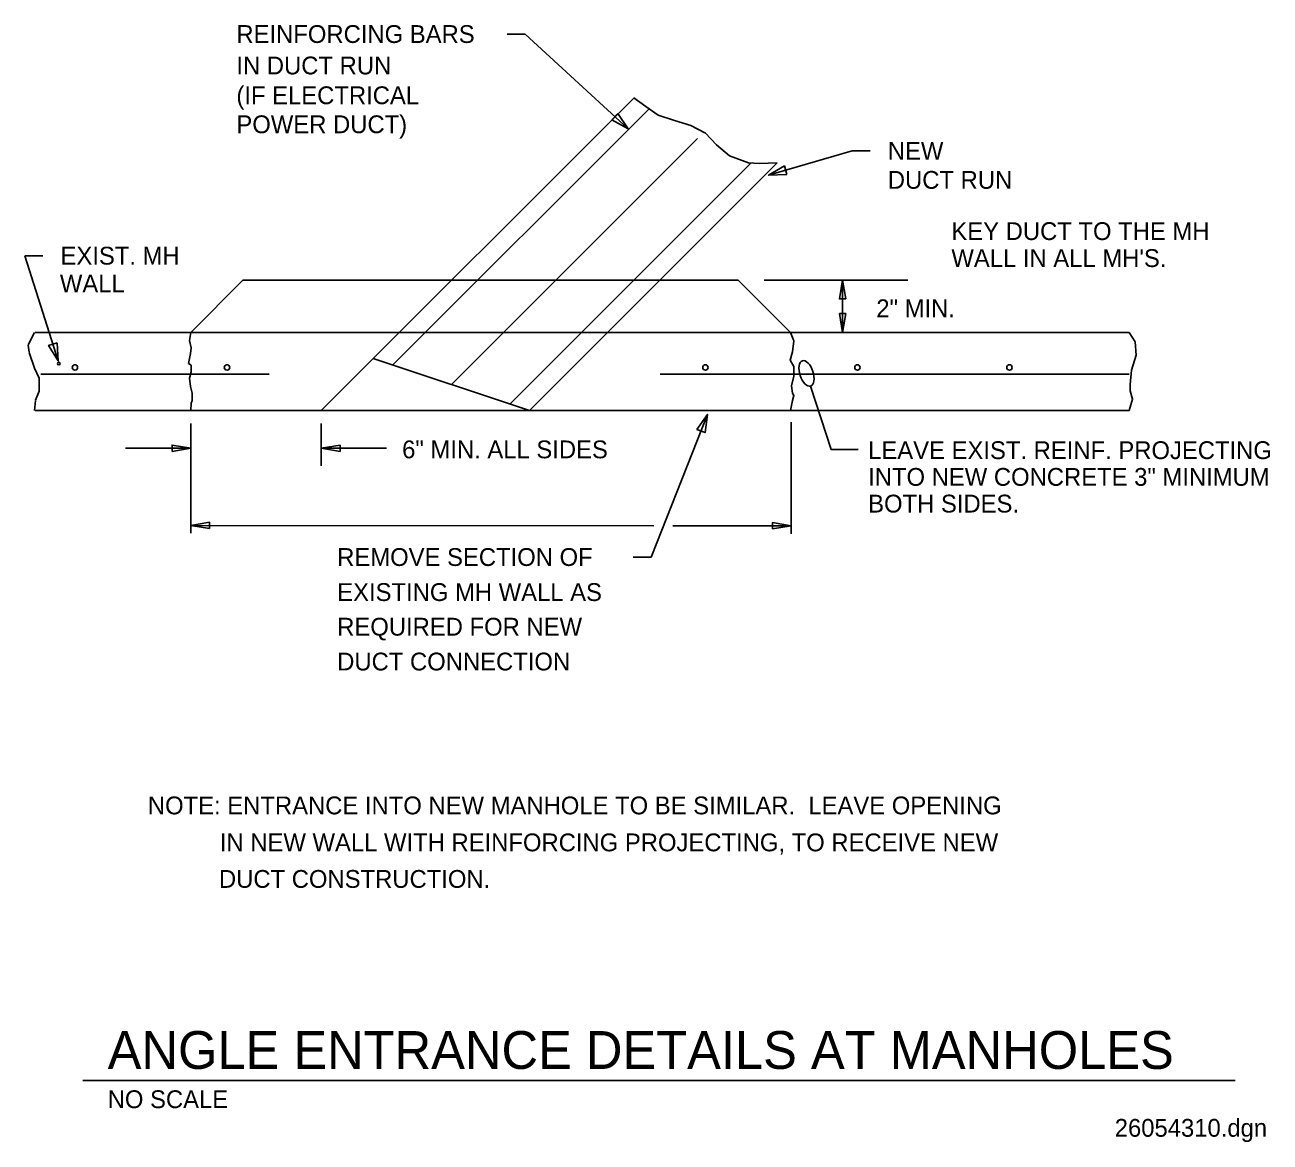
# Model space of a CAD drawing. Extents: x -12484.7 to -12438.1, y -12347.3 to -12305.5.
import ezdxf

# ---------------------------------------------------------------- set-up
doc = ezdxf.new("R2010")
doc.units = 0
for name, color, linetype in [('G-ANNO-TEXT', 7, 'Continuous'), ('G-DETL-LINE', 7, 'Continuous'), ('G-DETL-OTLN', 7, 'Continuous')]:
    doc.layers.add(name, color=color, linetype=linetype)

msp = doc.modelspace()

# ---------------------------------------------------------------- linework, layer by layer
at = {"layer": 'G-ANNO-TEXT'}
for p, q in [((-12466.688, -12305.829), (-12466.021, -12305.829)), ((-12466.021, -12305.829), (-12462.168, -12309.374)), ((-12453.78, -12310.201), (-12456.909, -12311.113)), ((-12453.113, -12310.201), (-12453.78, -12310.201)), ((-12484.072, -12314.128), (-12484.739, -12314.128)), ((-12484.739, -12314.128), (-12483.492, -12318.069)), ((-12457.071, -12315.044), (-12451.702, -12315.047)), ((-12478.532, -12320.412), (-12478.534, -12324.52)), ((-12473.649, -12320.412), (-12473.647, -12321.992)), ((-12461.304, -12325.411), (-12459.199, -12320.071)), ((-12456.059, -12320.361), (-12456.061, -12324.536)), ((-12478.534, -12324.224), (-12461.199, -12324.236)), ((-12460.487, -12324.236), (-12456.061, -12324.239)), ((-12461.971, -12325.411), (-12461.304, -12325.411)), ((-12482.57, -12345.009), (-12439.444, -12345.009))]:
    msp.add_line(p, q, dxfattribs=at)
for points in [[(-12462.545, -12308.8), (-12462.168, -12309.374), (-12462.771, -12309.045)], [(-12456.222, -12311.086), (-12456.909, -12311.113), (-12456.316, -12310.766)], [(-12454.024, -12315.746), (-12454.258, -12315.746), (-12454.141, -12315.044)], [(-12454.258, -12316.295), (-12454.024, -12316.295), (-12454.141, -12316.997)], [(-12483.534, -12317.384), (-12483.492, -12318.069), (-12483.852, -12317.484)], [(-12459.598, -12320.63), (-12459.199, -12320.071), (-12459.288, -12320.753)], [(-12479.234, -12321.455), (-12479.234, -12321.221), (-12478.532, -12321.338)], [(-12472.947, -12321.221), (-12472.947, -12321.455), (-12473.649, -12321.338)], [(-12477.832, -12324.107), (-12477.832, -12324.341), (-12478.534, -12324.224)], [(-12456.763, -12324.356), (-12456.763, -12324.122), (-12456.061, -12324.239)]]:
    msp.add_lwpolyline(points, close=True, dxfattribs=at)
for points in [[(-12454.141, -12315.044), (-12454.141, -12316.505), (-12454.141, -12316.997)], [(-12454.141, -12316.997), (-12454.141, -12315.537), (-12454.141, -12315.044)], [(-12453.562, -12321.39), (-12454.562, -12321.39), (-12455.335, -12319.011)], [(-12480.969, -12321.338), (-12479.508, -12321.338), (-12478.532, -12321.338)], [(-12471.211, -12321.338), (-12472.68, -12321.338), (-12473.649, -12321.338)]]:
    msp.add_lwpolyline(points, dxfattribs=at)
msp.add_ellipse((-12455.49, -12318.536), major_axis=(-0.155, 0.475), ratio=0.5, dxfattribs=at)
at = {"layer": 'G-DETL-LINE'}
for p, q in [((-12484.383, -12316.997), (-12484.614, -12317.471)), ((-12484.352, -12316.997), (-12443.414, -12316.999)), ((-12484.618, -12317.474), (-12484.582, -12317.743)), ((-12484.578, -12317.747), (-12484.374, -12318.343)), ((-12484.375, -12318.341), (-12484.206, -12318.719)), ((-12484.203, -12318.716), (-12484.206, -12319.199)), ((-12475.602, -12318.565), (-12484.142, -12318.565)), ((-12460.969, -12318.565), (-12443.414, -12318.565)), ((-12484.203, -12319.201), (-12484.342, -12319.543)), ((-12484.344, -12319.544), (-12484.382, -12319.919)), ((-12484.352, -12319.919), (-12443.414, -12319.919))]:
    msp.add_line(p, q, dxfattribs=at)
msp.add_lwpolyline([(-12443.414, -12316.997), (-12443.196, -12317.357), (-12443.149, -12317.857), (-12443.328, -12318.412), (-12443.375, -12318.951), (-12443.375, -12319.185), (-12443.289, -12319.497), (-12443.414, -12319.919)], dxfattribs=at)
for centre, radius, start, end in [((-12483.468, -12318.168), 0.0488, 0, 180), ((-12483.468, -12318.168), 0.0488, 180, 0), ((-12482.865, -12318.312), 0.1, 0, 180), ((-12482.865, -12318.312), 0.1, 180, 0), ((-12477.176, -12318.312), 0.1, 0, 180), ((-12477.176, -12318.312), 0.1, 180, 0), ((-12459.273, -12318.312), 0.1, 0, 180), ((-12459.273, -12318.312), 0.1, 180, 0), ((-12453.584, -12318.312), 0.1, 0, 180), ((-12453.584, -12318.312), 0.1, 180, 0), ((-12447.895, -12318.312), 0.1, 0, 180), ((-12447.895, -12318.312), 0.1, 180, 0)]:
    msp.add_arc(centre, radius, start, end, dxfattribs=at)
at = {"layer": 'G-DETL-OTLN'}
for p, q in [((-12473.649, -12319.919), (-12461.942, -12308.215)), ((-12470.969, -12318.216), (-12461.382, -12308.631)), ((-12468.777, -12318.947), (-12459.568, -12309.737)), ((-12466.578, -12319.677), (-12457.558, -12310.655)), ((-12465.852, -12319.919), (-12456.582, -12310.655)), ((-12478.532, -12316.997), (-12476.582, -12315.047)), ((-12476.578, -12315.044), (-12468.774, -12315.047)), ((-12468.774, -12315.044), (-12460.966, -12315.047)), ((-12460.969, -12315.044), (-12458.046, -12315.047)), ((-12458.047, -12315.044), (-12456.094, -12316.999)), ((-12465.852, -12319.919), (-12471.702, -12317.975))]:
    msp.add_line(p, q, dxfattribs=at)
for points in [[(-12461.946, -12308.216), (-12461.5, -12308.544), (-12461.047, -12308.872), (-12460.43, -12309.068), (-12459.821, -12309.255), (-12459.274, -12309.544), (-12458.852, -12309.974), (-12458.368, -12310.388), (-12457.657, -12310.646), (-12457.266, -12310.677), (-12456.586, -12310.654)], [(-12478.532, -12316.997), (-12478.578, -12317.302), (-12478.516, -12317.576), (-12478.547, -12317.787), (-12478.618, -12318.162), (-12478.516, -12318.232), (-12478.516, -12318.474), (-12478.578, -12318.716), (-12478.547, -12319.029), (-12478.477, -12319.271), (-12478.477, -12319.544), (-12478.516, -12319.646), (-12478.532, -12319.919)], [(-12456.094, -12316.997), (-12455.961, -12317.31), (-12456.008, -12317.724), (-12456.102, -12318.044), (-12455.961, -12318.271), (-12455.961, -12318.638), (-12456.055, -12318.997), (-12456.008, -12319.271), (-12455.961, -12319.365), (-12456.008, -12319.544), (-12456.094, -12319.919)]]:
    msp.add_lwpolyline(points, dxfattribs=at)

# ---------------------------------------------------------------- texts
at = {"layer": 'G-ANNO-TEXT'}
for s, height, p in [('REINFORCING BARS', 0.66667, (-12476.824, -12306.162)), ('IN DUCT RUN', 0.66667, (-12476.824, -12307.339)), ('(IF ELECTRICAL', 0.66667, (-12476.824, -12308.455)), ('POWER DUCT)', 0.66667, (-12476.824, -12309.541)), ('NEW', 0.6667, (-12452.447, -12310.535)), ('DUCT RUN', 0.6667, (-12452.447, -12311.622)), ('KEY DUCT TO THE MH', 0.66667, (-12450.068, -12313.541)), ('EXIST. MH', 0.6667, (-12483.406, -12314.461)), ("WALL IN ALL MH'S.", 0.66667, (-12450.068, -12314.551)), ('WALL', 0.6667, (-12483.43, -12315.503)), ('2" MIN.', 0.6667, (-12452.878, -12316.431)), ('6" MIN. ALL SIDES', 0.66667, (-12470.622, -12321.713)), ('LEAVE EXIST. REINF. PROJECTING', 0.66667, (-12453.183, -12321.743)), ('INTO NEW CONCRETE 3" MINIMUM', 0.66667, (-12453.183, -12322.743)), ('BOTH SIDES.', 0.66667, (-12453.183, -12323.743)), ('REMOVE SECTION OF', 0.66667, (-12473.052, -12325.744)), ('EXISTING MH WALL AS', 0.66667, (-12473.052, -12327.056)), ('REQUIRED FOR NEW', 0.66667, (-12473.052, -12328.352)), ('DUCT CONNECTION', 0.66667, (-12473.052, -12329.656)), ('NOTE: ENTRANCE INTO NEW MANHOLE TO BE SIMILAR.  LEAVE OPENING', 0.66667, (-12480.137, -12335.044)), ('      IN NEW WALL WITH REINFORCING PROJECTING, TO RECEIVE NEW', 0.66667, (-12478.928, -12336.428)), ('      DUCT CONSTRUCTION.', 0.66667, (-12478.963, -12337.796)), ('ANGLE ENTRANCE DETAILS AT MANHOLES', 1.41667, (-12481.641, -12344.576)), ('NO SCALE', 0.6667, (-12481.641, -12346.044)), ('26054310.dgn', 0.66667, (-12443.955, -12347.115))]:
    msp.add_text(s, height=height, dxfattribs=at).set_placement(p)

doc.saveas('drawing.dxf')
